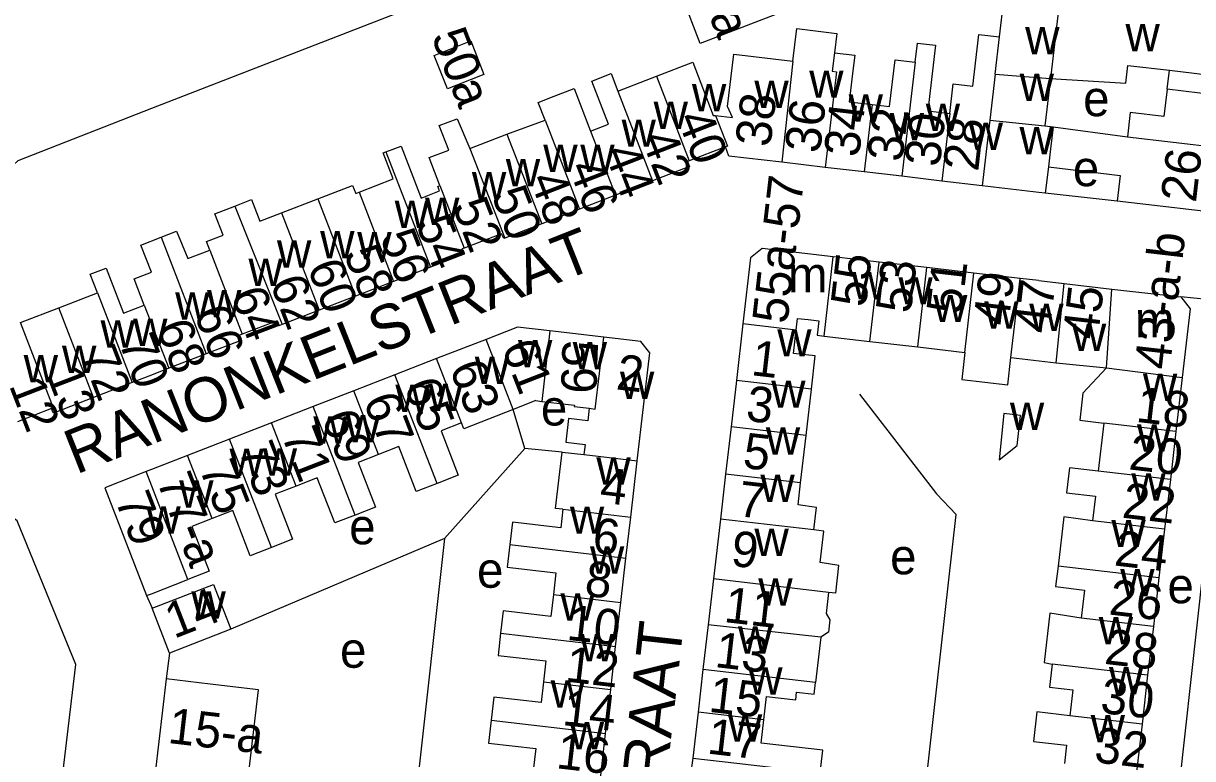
# Model space of a CAD drawing. Extents: x 161258 to 163262, y 380749 to 382054.
# Drawn here: x 161885.6 to 162017.3, y 381099.7 to 381182.5 of the extents above; entities that cross this region are included whole.
import ezdxf

# ---------------------------------------------------------------- set-up
doc = ezdxf.new("R2010")
doc.units = 0
for name, color, linetype in [('BLT_Basislijn', 7, 'Continuous'), ('BLT_Bebouwing', 7, 'Continuous'), ('BLT_Centroide', 7, 'Continuous'), ('BLT_Huisnummer', 7, 'Continuous'), ('BLT_Huisnummer_ tussenligend', 7, 'Continuous'), ('BLT_Huisnummer_reeks', 7, 'Continuous'), ('BLT_Huisnummer_zonder_bebouwing', 7, 'Continuous'), ('BLT_Onderdoorgang_en_onderverdeling', 7, 'Continuous'), ('BLT_Onderverdeling_panden', 7, 'Continuous'), ('BLT_Plantopo', 7, 'Continuous'), ('BLT_Straatnaam', 7, 'Continuous')]:
    doc.layers.add(name, color=color, linetype=linetype)

msp = doc.modelspace()

# ---------------------------------------------------------------- linework, layer by layer
at = {"layer": 'BLT_Basislijn'}
for p, q in [((162008.8, 381162.52), (162000.72, 381163.43)), ((161942.09, 381134.67), (161933.04, 381124.55)), ((161946.27, 381134.27), (161942.09, 381134.67)), ((161987.06, 381094.96), (161990.67, 381127.23)), ((161933.04, 381124.55), (161908.95, 381114.32)), ((161933.04, 381124.55), (161926.21, 381063.33)), ((161899.47, 381118.11), (161900.09, 381116.69)), ((161902.05, 381111.64), (161901.67, 381108.72)), ((161961, 381099.81), (161960.76, 381098.01))]:
    msp.add_line(p, q, dxfattribs=at)
for points in [[(161963.76, 381197.7), (161900, 381172.95), (161884.96, 381167.05), (161884, 381166.18), (161874.74, 381151.5)], [(162015.08, 381090.05), (162015.15, 381090.63), (162021.86, 381151.13), (162015.97, 381151.73)], [(161979.78, 381140.79), (161988.46, 381129.57), (161990.67, 381127.23)], [(161942.09, 381134.67), (161940.78, 381139.07)], [(161878.93, 381052.69), (161886.55, 381068.77), (161891.49, 381110.34), (161884.9, 381126.52), (161884.42, 381126.87), (161869.13, 381121.08), (161865.84, 381119.43), (161859.54, 381066.28), (161862.26, 381062.19), (161878.93, 381052.69)]]:
    msp.add_lwpolyline(points, dxfattribs=at)
at = {"layer": 'BLT_Bebouwing'}
for p, q in [((161961.83, 381180.27), (161956.83, 381193.26)), ((161977.22, 381181.42), (161976.96, 381179.23)), ((162014.45, 381175.12), (162014.7, 381177.27)), ((162000.66, 381171), (162001.59, 381170.89)), ((162001.59, 381170.89), (162009.96, 381169.76)), ((161964.67, 381168.63), (161960.59, 381167.05)), ((161960.59, 381167.05), (161960.4, 381166.98)), ((161975.92, 381166.33), (161971.02, 381166.9)), ((162001.06, 381166.37), (162000.72, 381163.43)), ((161980.32, 381165.81), (161975.92, 381166.33)), ((161984.55, 381165.32), (161980.32, 381165.81)), ((161989.07, 381164.79), (161984.55, 381165.32)), ((161956.48, 381164.8), (161952.28, 381163.18)), ((161993.61, 381164.26), (161989.07, 381164.79)), ((162000, 381163.51), (161993.61, 381164.26)), ((161914.67, 381161.21), (161918.76, 381162.79)), ((161952.28, 381163.18), (161948.25, 381161.62)), ((162000.72, 381163.43), (162000, 381163.51)), ((161948.25, 381161.62), (161943.98, 381159.97)), ((161939.44, 381158.86), (161935.25, 381157.24)), ((161935.25, 381157.24), (161935, 381157.15)), ((161935, 381157.15), (161935.23, 381156.55)), ((161935.23, 381156.55), (161931.44, 381155.08)), ((161982, 381155.66), (161976.83, 381156.26)), ((161931.44, 381155.08), (161927.3, 381153.48)), ((161987.38, 381155.04), (161982, 381155.66)), ((161992.68, 381154.42), (161987.38, 381155.04)), ((161927.3, 381153.48), (161923, 381151.82)), ((161997.88, 381153.82), (161992.68, 381154.42)), ((162000, 381153.58), (161997.88, 381153.82)), ((162000, 381153.58), (162002.85, 381153.25)), ((162002.85, 381153.25), (162008.22, 381152.62)), ((161889.59, 381150.51), (161893.94, 381152.19)), ((162008.22, 381152.62), (162015.97, 381151.73)), ((161923, 381151.82), (161918.91, 381150.24)), ((161885.26, 381148.84), (161889.59, 381150.51)), ((161914.19, 381149.05), (161910.25, 381147.53)), ((161941.26, 381148.35), (161937.71, 381146.96)), ((161944.9, 381147.92), (161941.26, 381148.35)), ((161966.65, 381148.69), (161965.92, 381142.34)), ((161909.91, 381146.77), (161906.18, 381145.33)), ((161910.25, 381147.53), (161909.7, 381147.32)), ((161909.91, 381146.77), (161909.7, 381147.32)), ((161937.71, 381146.96), (161932.14, 381144.8)), ((161980.96, 381146.73), (161986.34, 381146.11)), ((161906.18, 381145.33), (161901.96, 381143.7)), ((161986.34, 381146.11), (161991.66, 381145.49)), ((161932.14, 381144.8), (161927.45, 381142.97)), ((161996.84, 381144.9), (162001.96, 381144.3)), ((162001.96, 381144.3), (162007.6, 381143.74)), ((161927.45, 381142.97), (161922.8, 381141.16)), ((162016.14, 381142.68), (162015.43, 381136.58)), ((161897.83, 381142.1), (161893.48, 381140.42)), ((161965.92, 381142.34), (161965.31, 381137.11)), ((161973.77, 381136.13), (161974.37, 381141.36)), ((161922.8, 381141.16), (161918.22, 381139.38)), ((161943.33, 381140.06), (161940.78, 381139.07)), ((161943.33, 381140.06), (161943.98, 381139.98)), ((161888.75, 381139.16), (161884.91, 381137.67)), ((161918.22, 381139.38), (161913.55, 381137.56)), ((161943.98, 381139.98), (161947.66, 381139.55)), ((161913.55, 381137.56), (161908.79, 381135.71)), ((161996.05, 381138.6), (161995.51, 381133.38)), ((162007.31, 381137.52), (162006.69, 381132.12)), ((161965.31, 381137.11), (161964.7, 381131.79)), ((161973.15, 381130.81), (161973.77, 381136.13)), ((162015.43, 381136.58), (162014.81, 381131.18)), ((161908.79, 381135.71), (161904.09, 381133.88)), ((161946.27, 381134.27), (161948.72, 381133.98)), ((161954.01, 381126.93), (161954.75, 381133.28)), ((161964.7, 381131.79), (161964.11, 381126.72)), ((162014.81, 381131.18), (162014.16, 381125.6)), ((161953.47, 381122.32), (161954.01, 381126.93)), ((161964.11, 381126.72), (161963.33, 381119.98)), ((162014.16, 381125.6), (162013.52, 381120.11)), ((161952.89, 381117.33), (161953.47, 381122.32)), ((161963.33, 381119.98), (161962.73, 381114.8)), ((162013.52, 381120.11), (162012.89, 381114.62)), ((161977.11, 381118.38), (161976.31, 381118.47)), ((161902.05, 381111.64), (161900.09, 381116.69)), ((161952.31, 381112.36), (161952.89, 381117.33)), ((161908.95, 381114.32), (161902.05, 381111.64)), ((161962.73, 381114.8), (161962.15, 381109.78)), ((162012.89, 381114.62), (162012.25, 381109.13)), ((161951.75, 381107.52), (161952.31, 381112.36)), ((161975.43, 381113.44), (161974.84, 381108.32)), ((161962.15, 381109.78), (161961.6, 381104.97)), ((162012.25, 381109.13), (162011.62, 381103.64)), ((161951.18, 381102.58), (161951.75, 381107.52)), ((161961.6, 381104.97), (161961, 381099.81)), ((162011.62, 381103.64), (162010.99, 381098.26)), ((161950.59, 381097.51), (161951.18, 381102.58))]:
    msp.add_line(p, q, dxfattribs=at)
for points in [[(161966.59, 381195.96), (161971.23, 381183.89), (161961.83, 381180.27)], [(161995.57, 381181.01), (161996.06, 381185.14), (162002.23, 381184.39)], [(161972.29, 381178.28), (161972.72, 381181.95), (161977.22, 381181.42)], [(161989.95, 381172.39), (161990.34, 381175.72), (161992.54, 381175.46), (161993.22, 381181.29), (161995.57, 381181.01)], [(161986.06, 381178.16), (161986.31, 381180.31), (161988.36, 381180.07), (161987.49, 381172.68), (161989.95, 381172.39)], [(161963.57, 381172.15), (161965.46, 381171.93), (161964.93, 381173.19), (161965.62, 381179.06), (161972.29, 381178.28)], [(161976.96, 381179.23), (161979.24, 381178.96), (161978.99, 381176.88), (161978.62, 381173.7), (161981.21, 381173.4)], [(161981.21, 381173.4), (161983.18, 381173.17), (161983.79, 381178.43), (161986.06, 381178.16)], [(161949.48, 381170.4), (161951.52, 381171.19), (161949.64, 381176.05), (161951.8, 381176.89), (161952.57, 381174.9)], [(161956.9, 381176.59), (161960.99, 381178.18)], [(161960.99, 381178.18), (161963.29, 381172.18)], [(162001.29, 381176.34), (162009.78, 381175.8), (162010.02, 381177.81), (162014.7, 381177.27)], [(161952.57, 381174.9), (161956.9, 381176.59)], [(162001.29, 381176.34), (162000.66, 381171)], [(161944.37, 381171.64), (161943.59, 381173.65), (161945.4, 381174.36), (161947.62, 381175.22), (161949.48, 381170.4)], [(162014.45, 381175.12), (162014.09, 381172.06), (162010.29, 381172.51), (162009.96, 381169.76)], [(161932.52, 381164.28), (161931.3, 381167.44), (161933.5, 381168.27), (161932.44, 381171.03), (161934.44, 381171.8), (161935.89, 381168.46)], [(161940.06, 381170.07), (161944.37, 381171.64)], [(161963.29, 381172.18), (161963.57, 381172.15)], [(161935.89, 381168.46), (161940.06, 381170.07)], [(161927.26, 381165.03), (161926.13, 381167.96), (161926.42, 381168.07)], [(161926.42, 381168.07), (161928.13, 381168.71), (161930.4, 381162.86), (161932.48, 381163.67)], [(161971.02, 381166.9), (161965.07, 381167.6), (161964.67, 381168.63)], [(162024.27, 381168.09), (162023.53, 381161.84), (162022.38, 381160.93), (162008.8, 381162.52)], [(161960.4, 381166.98), (161960.62, 381166.41), (161956.48, 381164.8)], [(162001.06, 381166.37), (162009.14, 381165.43), (162008.8, 381162.52)], [(161923.41, 381163.54), (161927.26, 381165.03)], [(161918.76, 381162.79), (161922.68, 381164.3), (161923.03, 381163.4), (161923.41, 381163.54)], [(161932.48, 381163.67), (161932.28, 381164.19), (161932.52, 381164.28)], [(161909.41, 381161.97), (161911.28, 381162.7), (161912.23, 381160.27), (161914.67, 381161.21)], [(161906.6, 381157.02), (161906.23, 381157.99), (161908.09, 381158.7), (161907.17, 381161.11), (161909.41, 381161.97)], [(161943.98, 381159.97), (161939.81, 381158.34)], [(161899.21, 381150.81), (161898.07, 381153.76), (161900, 381154.51), (161898.82, 381157.57), (161901.11, 381158.46)], [(161901.11, 381158.46), (161902.85, 381159.13), (161904.12, 381156.08), (161906.6, 381157.02)], [(161939.81, 381158.34), (161939.7, 381158.3), (161939.44, 381158.86)], [(161976.83, 381156.26), (161968.83, 381157.18), (161967.51, 381156.14), (161966.65, 381148.69)], [(161893.94, 381152.19), (161893.12, 381154.3), (161894.92, 381154.99), (161896.88, 381149.92), (161899.21, 381150.81)], [(162015.97, 381151.73), (162017.03, 381150.38), (162016.14, 381142.68)], [(161918.91, 381150.24), (161914.73, 381148.62)], [(161972.66, 381148), (161972.81, 381149.32), (161974.01, 381149.18)], [(161914.73, 381148.62), (161914.36, 381148.48), (161914.19, 381149.05)], [(161950.97, 381147.22), (161944.9, 381147.92)], [(161974.37, 381141.36), (161974.8, 381145.1), (161972.36, 381145.38), (161972.66, 381148)], [(161974.01, 381149.18), (161975.21, 381149.04), (161975.02, 381147.42), (161975.82, 381147.33)], [(161954.75, 381133.28), (161956.16, 381145.46), (161955.15, 381146.73), (161950.97, 381147.22)], [(161975.82, 381147.33), (161980.96, 381146.73)], [(161991.66, 381145.49), (161991.32, 381142.44), (161996.49, 381141.84), (161996.84, 381144.9)], [(161901.96, 381143.7), (161900, 381142.94), (161897.83, 381142.1)], [(162007.6, 381143.74), (162004.94, 381140.9), (162004.59, 381137.87), (162007.31, 381137.52)], [(161893.48, 381140.42), (161889.15, 381138.74)], [(161889.14, 381138.74), (161888.94, 381138.67), (161888.75, 381139.16)], [(161940.78, 381139.07), (161935.21, 381136.9), (161934.95, 381137.56)], [(161949.33, 381139.2), (161949.17, 381137.78), (161946.99, 381138.05), (161946.68, 381135.38), (161948.86, 381135.11), (161948.72, 381133.98)], [(161947.66, 381139.55), (161947.65, 381139.39), (161949.33, 381139.2)], [(161934.95, 381137.56), (161932.64, 381136.66), (161934.58, 381131.67), (161932.21, 381130.74)], [(161995.51, 381133.38), (161997.55, 381134.99), (161997.94, 381138.38), (161996.05, 381138.6)], [(161932.21, 381130.74), (161929.84, 381129.82), (161927.87, 381134.88), (161925.59, 381133.99)], [(161904.09, 381133.88), (161900, 381132.29), (161899.41, 381132.06)], [(161925.59, 381133.99), (161923.31, 381133.1), (161925.27, 381128.08), (161922.97, 381127.18)], [(161946.36, 381127.82), (161945.53, 381127.92), (161946.27, 381134.27)], [(162006.69, 381132.12), (162003.44, 381132.5), (162003.11, 381129.67), (162006.36, 381129.29), (162006.04, 381126.54)], [(161899.41, 381132.06), (161894.75, 381130.24), (161899.47, 381118.11)], [(161922.97, 381127.18), (161920.67, 381126.29), (161918.69, 381131.36), (161916.32, 381130.44)], [(161974.64, 381125.5), (161974.93, 381128.04), (161972.86, 381128.32), (161973.15, 381130.81)], [(161916.32, 381130.44), (161913.95, 381129.52), (161915.91, 381124.46), (161913.53, 381123.53)], [(161913.53, 381123.53), (161911.14, 381122.6), (161909.17, 381127.67), (161906.86, 381126.77)], [(161946.36, 381127.82), (161946.12, 381125.74), (161940.69, 381126.38), (161940.39, 381123.84)], [(162006.04, 381126.54), (162002.8, 381126.99), (162002.15, 381121.43)], [(161906.86, 381126.77), (161904.55, 381125.88), (161906.51, 381120.85), (161904.13, 381119.93)], [(161977.11, 381118.38), (161977.47, 381121.51), (161975.37, 381121.82), (161975.77, 381125.37), (161974.64, 381125.5)], [(161940.39, 381123.84), (161940.1, 381121.31), (161945.59, 381120.68), (161945.3, 381118.22)], [(162002.15, 381121.43), (162001.88, 381119.11), (162005.13, 381118.73), (162004.77, 381115.56)], [(161899.47, 381118.11), (161900, 381118.32), (161904.13, 381119.93)], [(161900.09, 381116.69), (161906.99, 381119.37), (161908.95, 381114.32)], [(161945.3, 381118.22), (161945.02, 381115.76), (161939.65, 381116.38), (161939.35, 381113.87)], [(161976.31, 381118.47), (161976.03, 381116.08), (161976.45, 381115.37), (161976.29, 381113.99), (161975.43, 381113.44)], [(162004.77, 381115.56), (162001.23, 381116.13), (162000.58, 381110.56), (162001.49, 381110.38)], [(161939.35, 381113.87), (161939.06, 381111.36), (161944.46, 381110.74), (161944.19, 381108.39)], [(162001.49, 381110.38), (162001.19, 381107.81), (162003.83, 381107.5), (162003.49, 381104.58)], [(161901.67, 381108.72), (161900, 381094.61), (161897.36, 381072.21)], [(161907.78, 381070.98), (161912.09, 381107.49), (161906.61, 381108.14), (161901.67, 381108.72)], [(161944.19, 381108.39), (161943.92, 381106.05), (161938.59, 381106.67), (161938.29, 381104.08)], [(161968.99, 381104.11), (161969.3, 381106.74), (161972.6, 381106.35), (161972.7, 381107.23), (161974.69, 381107), (161974.84, 381108.32)], [(162003.49, 381104.58), (161999.78, 381105.01), (161999.39, 381101.69), (162003.11, 381101.26), (162002.87, 381099.2)], [(161938.29, 381104.08), (161937.99, 381101.49), (161943.32, 381100.87), (161943.03, 381098.39)], [(161961, 381099.81), (161965.97, 381099.24), (161975.35, 381098.16), (161975.64, 381100.68), (161968.69, 381101.49), (161968.99, 381104.11)]]:
    msp.add_lwpolyline(points, dxfattribs=at)
at = {"layer": 'BLT_Onderdoorgang_en_onderverdeling'}
for points in [[(162014.7, 381177.27), (162020.25, 381176.61), (162025.21, 381176.03)], [(162024.94, 381173.89), (162019.98, 381174.47), (162014.45, 381175.12)]]:
    msp.add_lwpolyline(points, dxfattribs=at)
at = {"layer": 'BLT_Onderverdeling_panden'}
for p, q in [((162002.23, 381184.39), (162001.29, 381176.34)), ((161995.08, 381176.84), (161995.57, 381181.01)), ((161972.29, 381178.28), (161971.02, 381166.9)), ((161977.18, 381177.09), (161975.92, 381166.33)), ((161986.06, 381178.16), (161984.55, 381165.32)), ((161956.9, 381176.59), (161960.59, 381167.05)), ((161995.08, 381176.84), (161994.48, 381171.66)), ((161995.08, 381176.84), (162001.29, 381176.34)), ((161952.57, 381174.9), (161956.48, 381164.8)), ((161981.21, 381173.4), (161980.32, 381165.81)), ((161944.37, 381171.64), (161948.25, 381161.62)), ((161989.95, 381172.39), (161989.07, 381164.79)), ((161994.48, 381171.66), (161993.61, 381164.26)), ((161994.48, 381171.66), (162000.66, 381171)), ((161949.48, 381170.4), (161952.28, 381163.18)), ((161940.06, 381170.07), (161943.98, 381159.97)), ((162009.96, 381169.76), (162024.27, 381168.09)), ((161926.42, 381168.07), (161931.44, 381155.08)), ((161935.89, 381168.46), (161939.81, 381158.34)), ((161932.52, 381164.28), (161935.25, 381157.24)), ((161918.76, 381162.79), (161923, 381151.82)), ((161923.41, 381163.54), (161927.3, 381153.48)), ((161909.41, 381161.97), (161914.73, 381148.62)), ((161914.67, 381161.21), (161918.91, 381150.24)), ((161901.11, 381158.46), (161906.18, 381145.33)), ((161906.6, 381157.02), (161910.25, 381147.53)), ((161975.82, 381147.33), (161976.83, 381156.26)), ((161980.96, 381146.73), (161982, 381155.66)), ((161986.34, 381146.11), (161987.38, 381155.04)), ((161991.66, 381145.49), (161992.68, 381154.42)), ((161996.84, 381144.9), (161997.88, 381153.82)), ((161893.94, 381152.19), (161897.83, 381142.1)), ((162007.6, 381143.74), (162008.22, 381152.62)), ((161899.21, 381150.81), (161901.96, 381143.7)), ((161893.48, 381140.42), (161889.59, 381150.51)), ((161889.15, 381138.74), (161885.26, 381148.84)), ((161944.9, 381147.92), (161943.98, 381139.98)), ((161972.66, 381148), (161966.65, 381148.69)), ((161940.78, 381139.07), (161937.71, 381146.96)), ((161934.95, 381137.56), (161932.14, 381144.8)), ((161932.21, 381130.74), (161927.45, 381142.97)), ((162007.6, 381143.74), (162016.14, 381142.68)), ((161974.37, 381141.36), (161965.92, 381142.34)), ((161925.59, 381133.99), (161922.8, 381141.16)), ((161922.97, 381127.18), (161918.22, 381139.38)), ((161916.32, 381130.44), (161913.55, 381137.56)), ((162015.43, 381136.58), (162007.31, 381137.52)), ((161973.77, 381136.13), (161965.31, 381137.11)), ((161913.53, 381123.53), (161908.79, 381135.71)), ((161906.86, 381126.77), (161904.09, 381133.88)), ((161948.72, 381133.98), (161949.42, 381133.9)), ((161949.42, 381133.9), (161954.75, 381133.28)), ((162014.81, 381131.18), (162006.69, 381132.12)), ((161904.13, 381119.93), (161899.41, 381132.06)), ((161973.15, 381130.81), (161964.7, 381131.79)), ((161946.36, 381127.82), (161954.01, 381126.93)), ((161974.64, 381125.5), (161964.11, 381126.72)), ((162014.16, 381125.6), (162006.04, 381126.54)), ((161940.39, 381123.84), (161953.47, 381122.32)), ((162013.52, 381120.11), (162002.15, 381121.43)), ((161976.31, 381118.47), (161963.33, 381119.98)), ((161945.3, 381118.22), (161952.89, 381117.33)), ((162012.89, 381114.62), (162004.77, 381115.56)), ((161939.35, 381113.87), (161952.31, 381112.36)), ((161975.43, 381113.44), (161962.73, 381114.8)), ((161974.84, 381108.32), (161962.15, 381109.78)), ((162012.25, 381109.13), (162001.49, 381110.38)), ((161944.19, 381108.39), (161951.75, 381107.52)), ((161968.99, 381104.11), (161961.6, 381104.97)), ((162011.62, 381103.64), (162003.49, 381104.58)), ((161938.29, 381104.08), (161951.18, 381102.58))]:
    msp.add_line(p, q, dxfattribs=at)
for points in [[(161976.96, 381179.23), (161976.71, 381177.15), (161977.18, 381177.09)], [(161963.57, 381172.15), (161964.9, 381168.71), (161964.67, 381168.63)], [(162001.59, 381170.89), (162001.3, 381168.4), (162001.06, 381166.37)], [(162001.96, 381144.3), (162002.85, 381153.25)], [(161949.33, 381139.2), (161950.02, 381139.11), (161950.97, 381147.22)]]:
    msp.add_lwpolyline(points, dxfattribs=at)
at = {"layer": 'BLT_Plantopo'}
msp.add_lwpolyline([(161935.99, 381180.58), (161937.45, 381176.79), (161933.35, 381175.17), (161931.86, 381178.94)], close=True, dxfattribs=at)

# ---------------------------------------------------------------- texts
at = {"layer": 'BLT_Centroide'}
for s, p in [('w', (162009.75, 381179.39)), ('w', (161998.45, 381179.06)), ('w', (161974.12, 381174.16)), ('w', (161997.83, 381173.81)), ('w', (161960.91, 381172.64)), ('w', (161967.94, 381173.02)), ('w', (161978.56, 381171.48)), ('e', (162004.98, 381172.09)), ('w', (161956.59, 381170.66)), ('w', (161987.25, 381170.44)), ('w', (161952.98, 381168.64)), ('w', (161983.19, 381169.38)), ('w', (161992.08, 381168.3)), ('w', (161997.81, 381167.81)), ('w', (161944.16, 381165.8)), ('w', (161948.33, 381165.81)), ('w', (161939.94, 381164.19)), ('e', (162003.82, 381164.21)), ('w', (161936.12, 381162.72)), ('w', (161927.42, 381159.5)), ('w', (161930.84, 381159.84)), ('w', (161919.02, 381156.08)), ('w', (161923.2, 381155.97)), ('w', (161914.16, 381155.02)), ('w', (161910.95, 381152.97)), ('m', (161971.72, 381152.25)), ('w', (161978.91, 381151.48)), ('w', (161984.17, 381150.89)), ('w', (161902.69, 381149.17)), ('w', (161906.28, 381149.44)), ('w', (161988.08, 381148.9)), ('w', (161993.84, 381148.17)), ('w', (161998.91, 381147.9)), ('w', (161897.95, 381146.23)), ('m', (162010.81, 381147.18)), ('w', (161894.28, 381146.02)), ('w', (161970.52, 381145.03)), ('w', (162003.72, 381145.66)), ('w', (161941.31, 381143.81)), ('w', (161947.47, 381143.59)), ('w', (161889.94, 381143.16)), ('w', (161885.62, 381142.11)), ('w', (161936.45, 381141.92)), ('w', (161952.8, 381140.25)), ('w', (162011.72, 381140.03)), ('w', (161927.5, 381138.78)), ('w', (161931.2, 381138.89)), ('w', (161969.84, 381139.25)), ('e', (161943.89, 381137.26)), ('w', (161996.73, 381136.77)), ('w', (161918.25, 381135.23)), ('w', (161921.91, 381135.36)), ('w', (162011.05, 381134.31)), ('w', (161969.23, 381133.97)), ('w', (161908.81, 381131.59)), ('w', (161912.55, 381131.61)), ('w', (161950.14, 381130.59)), ('w', (161903.14, 381128)), ('w', (161968.62, 381128.66)), ('w', (162010.41, 381128.81)), ('w', (161899.44, 381125.08)), ('e', (161922.29, 381123.88)), ('w', (161947.16, 381125.06)), ('w', (161967.95, 381122.56)), ('w', (162008.16, 381123.56)), ('w', (161949.42, 381120.59)), ('e', (161983.23, 381120.5)), ('e', (161936.69, 381118.99)), ('w', (162009.16, 381118.03)), ('e', (162014.48, 381117.24)), ('w', (161968.38, 381116.97)), ('w', (161904.52, 381115.5)), ('w', (161946.09, 381115.28)), ('w', (162006.74, 381112.62)), ('w', (161948.29, 381110.69)), ('w', (161966.1, 381111.56)), ('e', (161921.26, 381109.98)), ('w', (161967.25, 381106.94)), ('w', (162007.89, 381107)), ('w', (161944.98, 381105.5)), ('w', (161964.96, 381101.66)), ('w', (162005.83, 381101.59)), ('w', (161947.14, 381100.78))]:
    msp.add_text(s, height=4, dxfattribs=at).set_placement(p)
at = {"layer": 'BLT_Huisnummer'}
for s, rotation, p in [('38a', 291.2217, (161960.68, 381188.91)), ('38', 83.3121, (161969.74, 381168.53)), ('40', 291.2217, (161959.18, 381171.87)), ('32', 83.3068, (161984.6, 381166.86)), ('28', 83.422, (161993.15, 381165.79)), ('44', 291.1401, (161950.98, 381168.07)), ('26', 83.3291, (162017.68, 381162.28)), ('48', 291.1529, (161942.57, 381165)), ('52', 291.1529, (161933.88, 381162)), ('56', 291.1518, (161925.72, 381158.47)), ('60', 291.1456, (161917.53, 381155.1)), ('55', 83.3606, (161980.49, 381150.51)), ('51', 83.3606, (161991.27, 381149.7)), ('47', 83.3638, (162001.19, 381147.52)), ('64', 290.8967, (161908.88, 381152.01)), ('68', 290.8976, (161900.5, 381148.33)), ('59', 268.0978, (161946.34, 381146.89)), ('1', 353.4062, (161967.48, 381142.94)), ('72', 291.1414, (161892.02, 381145.29)), ('63', 291.2708, (161933.54, 381143.73)), ('2', 353.3791, (161952.27, 381141.34)), ('13', 291.0246, (161888.12, 381143.07)), ('12', 291.1442, (161883.93, 381141.79)), ('18', 353.3884, (162010.84, 381137.68)), ('67', 291.2705, (161923.83, 381140.06)), ('71', 291.2648, (161914.63, 381136.17)), ('5', 353.4062, (161966.54, 381132.5)), ('75', 291.2581, (161905.36, 381132.46)), ('22', 353.3884, (162009.27, 381126.89)), ('79', 291.2678, (161895.87, 381128.89)), ('6', 353.3667, (161949.57, 381122.96)), ('9', 353.3999, (161965.19, 381121.48)), ('26', 353.3875, (162007.79, 381115.99)), ('14', 21.2631, (161902.55, 381113.22)), ('10', 353.3689, (161946.7, 381113.14)), ('13', 353.4186, (161963.39, 381110.07)), ('30', 353.3867, (162006.82, 381104.91)), ('14', 353.3658, (161946.21, 381103.54)), ('17', 353.408, (161962.53, 381100.33))]:
    msp.add_text(s, height=4, rotation=rotation, dxfattribs=at).set_placement(p)
at = {"layer": 'BLT_Huisnummer_ tussenligend'}
for s, rotation, p in [('36', 83.3121, (161975.32, 381167.84)), ('34', 83.3068, (161979.72, 381167.39)), ('30', 83.422, (161988.81, 381166.3)), ('42', 291.2217, (161955.14, 381169.6)), ('46', 291.1401, (161946.95, 381166.33)), ('50', 291.1529, (161938.26, 381163.31)), ('54', 291.1529, (161929.74, 381160.06)), ('58', 291.1518, (161921.64, 381156.64)), ('53', 83.3606, (161985.56, 381149.81)), ('62', 291.1456, (161913.33, 381153.31)), ('49', 83.3638, (161996.56, 381148.41)), ('45', 83.3872, (162006.63, 381146.85)), ('66', 290.8967, (161904.75, 381149.93)), ('70', 290.8976, (161896.3, 381146.65)), ('61', 291.2708, (161939.42, 381146.05)), ('65', 291.2708, (161928.41, 381141.73)), ('3', 353.4062, (161966.89, 381137.81)), ('69', 291.2705, (161919.14, 381138.14)), ('20', 353.3884, (162010.03, 381132.33)), ('73', 291.2648, (161909.78, 381134.51)), ('4', 353.3791, (161950.42, 381128.6)), ('7', 353.4062, (161965.98, 381127.07)), ('24', 353.3884, (162008.39, 381121.51)), ('8', 353.3667, (161948.71, 381118.1)), ('11', 353.3999, (161964.42, 381115.14)), ('28', 353.3875, (162007.28, 381110.43)), ('12', 353.3689, (161946.54, 381108.44)), ('15', 353.4186, (161962.7, 381105.03)), ('32', 353.3867, (162006.13, 381099.35)), ('16', 353.3658, (161945.52, 381098.68))]:
    msp.add_text(s, height=4, rotation=rotation, dxfattribs=at).set_placement(p)
at = {"layer": 'BLT_Huisnummer_reeks'}
for s, rotation, p in [('55a-57', 83.4065, (161971.65, 381148.62)), ('43-a-b', 83.3841, (162014.73, 381143.45)), ('77-a', 291.2581, (161900.57, 381131.03)), ('15-a', 353.4025, (161901.76, 381101.52))]:
    msp.add_text(s, height=4, rotation=rotation, dxfattribs=at).set_placement(p)
at = {"layer": 'BLT_Huisnummer_zonder_bebouwing'}
msp.add_text('50a', height=4, rotation=291.1529, dxfattribs=at).set_placement((161931.51, 381181.1))
at = {"layer": 'BLT_Straatnaam'}
for s, height, rotation, p in [('RANONKELSTRAAT', 4.9999, 21.6629, (161891.52, 381131.71)), ('FUCHSIASTRAAT', 5, 83.6596, (161953.83, 381059.48)), ('HORTENSIASTRAAT', 5, 83.4116, (162017.15, 381036.41))]:
    msp.add_text(s, height=height, rotation=rotation, dxfattribs=at).set_placement(p)

doc.saveas('drawing.dxf')
